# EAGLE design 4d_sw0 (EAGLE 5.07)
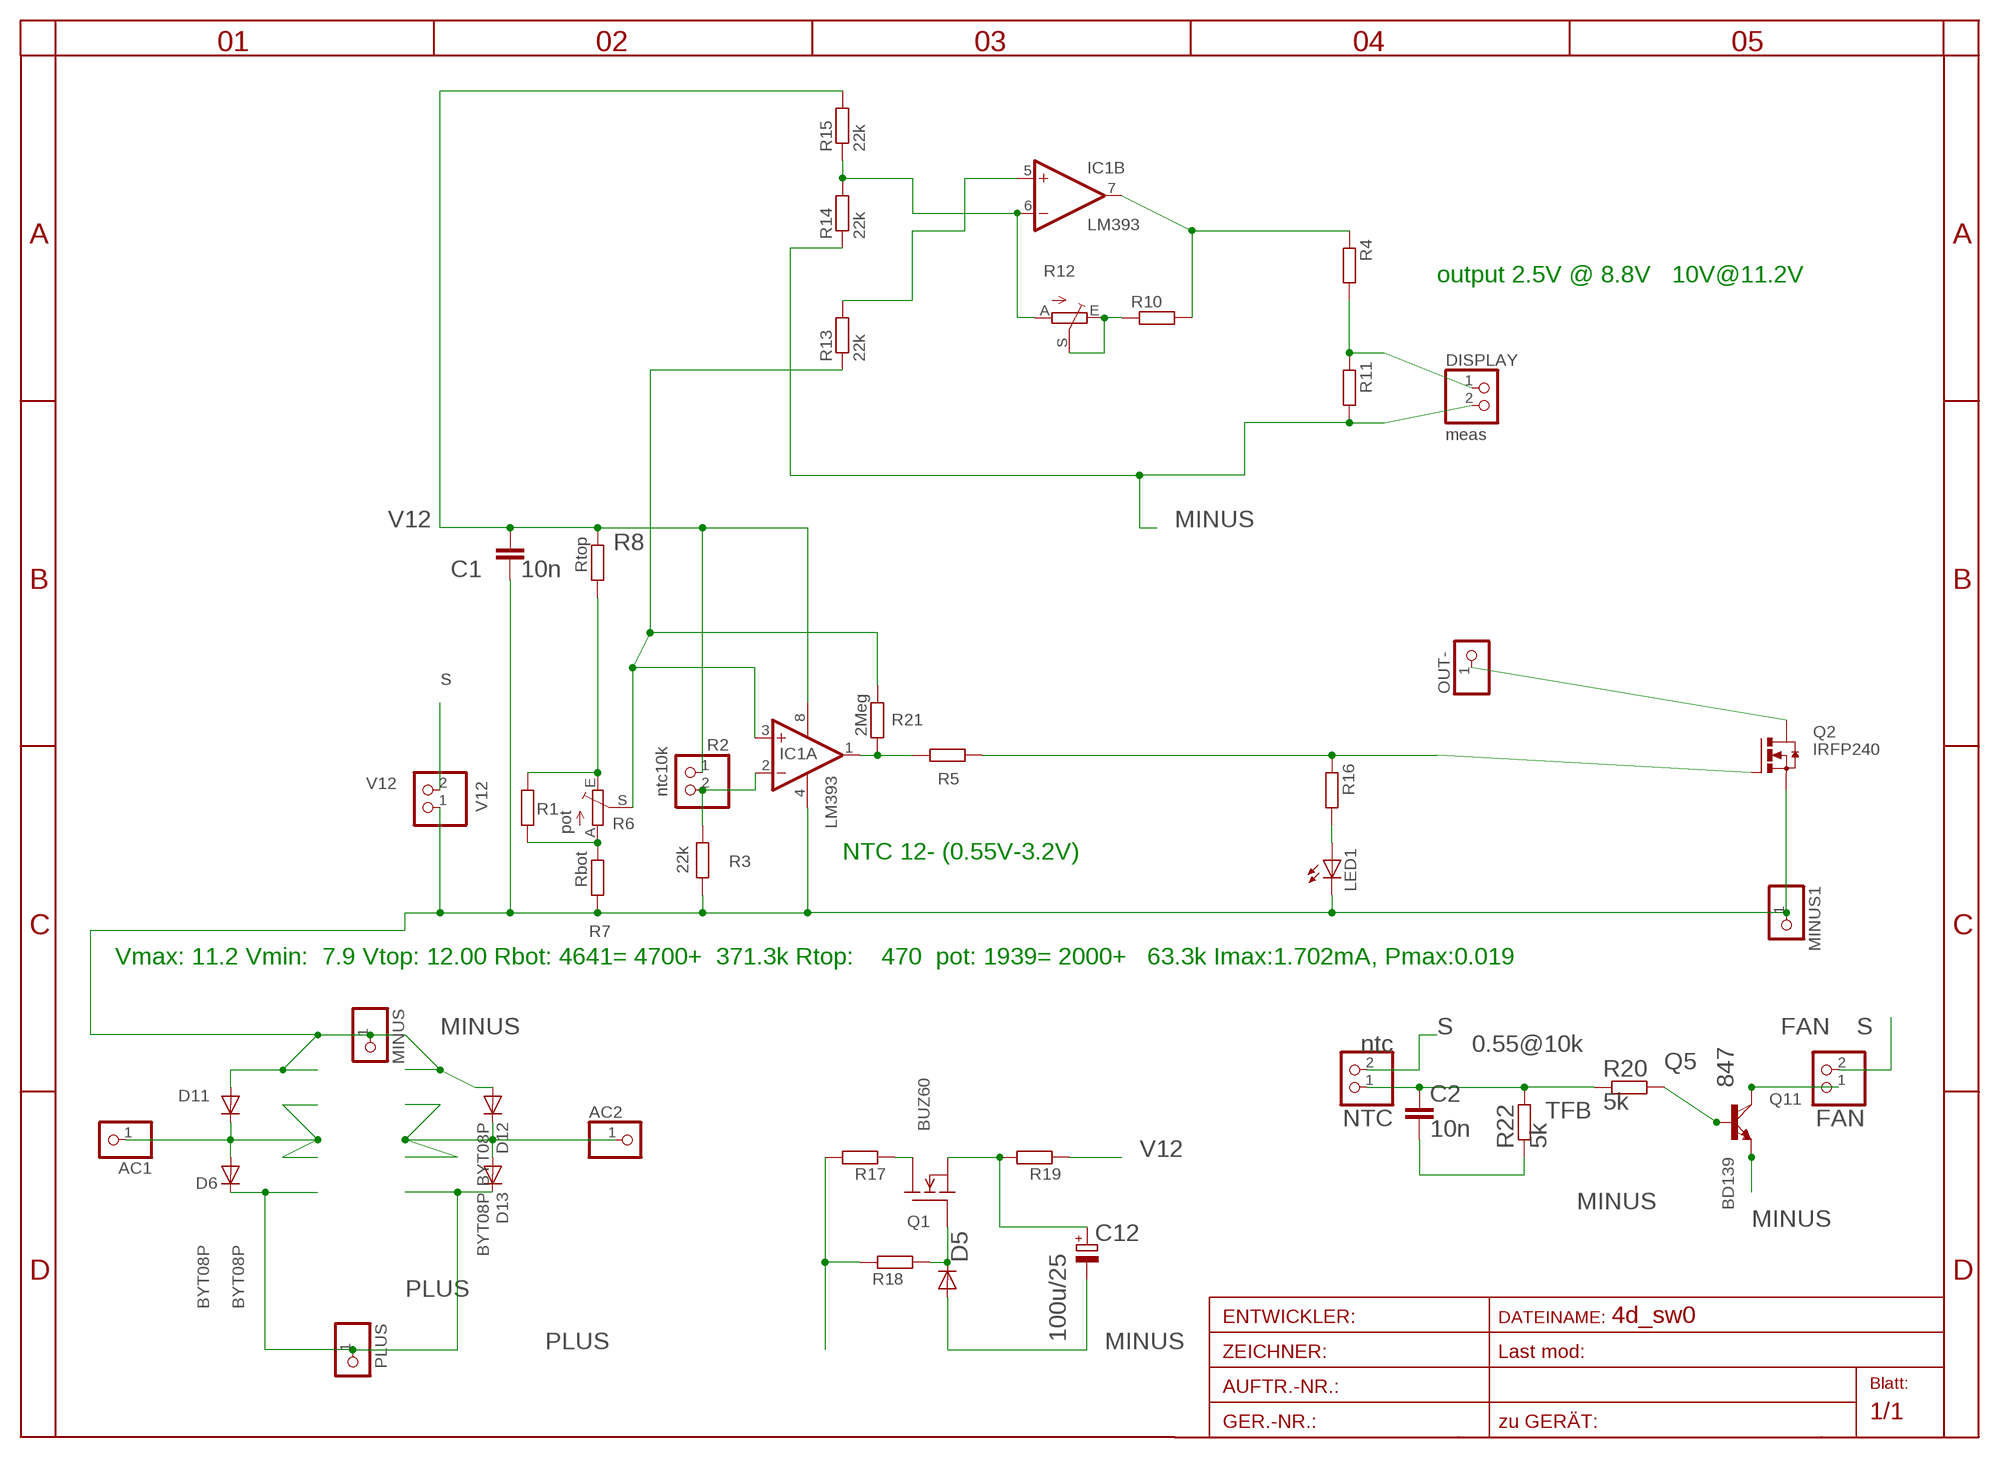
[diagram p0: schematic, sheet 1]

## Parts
AC1  PINHD-1X12MM2  [1X2MM2]
AC2  PINHD-1X12MM2  [1X2MM2]
C1  10n  C-EUC0805  [C0805]
C2  10n  C-EUC0805  [C0805]
C12  100u/25  CPOL-EUD  [PANASONIC_D]
D5  DIODE-MINIMELF  [MINIMELF]
D6  BYT08P  [TO220ACS]
D11  BYT08P  [TO220ACS]
D12  BYT08P  [TO220ACS]
D13  BYT08P  [TO220ACS]
DISPLAY  meas  PINHD-1X2STR  [1X02]
FAN  FAN  PINHD-1X2STR  [1X02]
IC1  LM393  LM358D  [SO08]
LED1  LEDSMT1206  [1206]
MINUS  PINHD-1X12MM2  [1X2MM2]
MINUS1  PINHD-1X12MM2  [1X2MM2]
NTC  ntc  PINHD-1X2STR  [1X02]
OUT-  PINHD-1X12MM2  [1X2MM2]
PLUS  PINHD-1X12MM2  [1X2MM2]
Q1  BUZ60  [TO220]
Q2  IRFP240  [TO247BV]
Q5  847  BC847SMD  [SOT23]
Q11  BD139  [TO126AV]
R1  R-EU_R1206  [R1206]
R2  ntc10k  PINHD-1X2STR  [1X02]
R3  22k  R-EU_R1206  [R1206]
R4  R-EU_R0805  [R0805]
R5  R-EU_0207-17  [0207/17]
R6  pot  TRIM_EU-RAND160  [RANDL]
R7  Rbot  R-EU_R1206  [R1206]
R8  Rtop  R-EU_R1206  [R1206]
R10  R-EU_R0805  [R0805]
R11  R-EU_R0805  [R0805]
R12  TRIM_EU-CA6V  [CA6V]
R13  22k  R-EU_R0805  [R0805]
R14  22k  R-EU_R0805  [R0805]
R15  22k  R-EU_R1206  [R1206]
R16  R-EU_R1206  [R1206]
R17  R-EU_0207/10  [0207/10]
R18  R-EU_0207/12  [0207/12]
R19  R-EU_0204/7  [0204/7]
R20  5k  R-EU_R0805  [R0805]
R21  2Meg  R-EU_R1206  [R1206]
R22  5k  R-EU_R0805  [R0805]
V12  V12  PINHD-1X2STR  [1X02]

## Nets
A: R1.2 R6.A R7.1
AC1: AC1.1 D6.A D11.C
AC2: AC2.1 D12.C D13.A
E: R1.1 R6.E R8.2
KKK: IC1.6(B:-IN) R12.A R14.2 R15.1
MINUS: C1.2 C2.2 C12.- D5.A D11.A D12.A DISPLAY.2 IC1.4(P:V-) LED1.C MINUS1.1 MINUS.1 Q2.S Q5.2(E) Q11.E R3.2 R7.2 R11.2 R14.1 R22.1 V12.1
N$1: DISPLAY.1 R4.2 R11.1
N$3: IC1.1(A:OUT) R5.2 R21.2
N$4: R10.1 R12.E R12.S
N$5: IC1.2(A:-IN) R2.2 R3.1
N$6: Q2.G R5.1 R16.1
N$7: FAN.1 Q5.3(C) Q11.C
N$8: OUT-.1 Q2.D
N$9: IC1.3(A:+IN) R6.S R13.1 R21.1
N$10: Q1.2(D) R17.1
N$11: IC1.7(B:OUT) R4.1 R10.2
N$12: D5.C Q1.1(G) R18.1
N$13: Q5.1(B) Q11.B R20.2
N$14: LED1.A R16.2
N$16: IC1.5(B:+IN) R13.2
PLUS: D6.C D13.C PLUS.1 R17.2 R18.2
S: C12.+ FAN.2 NTC.2 Q1.3(S) R19.2 V12.2
TFB: C2.1 NTC.1 R20.1 R22.2
V12: C1.1 IC1.8(P:V+) R2.1 R8.1 R15.2 R19.1

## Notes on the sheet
- output 2.5V @ 8.8V   10V@11.2V
- NTC 12- (0.55V-3.2V)
- Vmax: 11.2 Vmin:  7.9 Vtop: 12.00 Rbot: 4641= 4700+  371.3k Rtop:    470  pot: 1939= 2000+   63.3k Imax:1.702mA, Pmax:0.019
- 0.55@10k

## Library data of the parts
AC1 AC2 MINUS MINUS1 OUT- PLUS = pinhead:PINHD-1X1: PIN HEADER
C1 C2 = rcl:C-EU: CAPACITOR, European symbol
C12 = rcl:CPOL-EU: POLARIZED CAPACITOR, European symbol
D5 = diode:DIODE-: DIODE
D6 D11-D13 = diode:BYT08P: DIODE
DISPLAY FAN NTC R2 V12 = pinhead:PINHD-1X2: PIN HEADER
IC1 = linear:LM358: OP AMP also LM158; LM258; LM2904 Source: http://cache.national.com/ds/LM/LM158.pdf
LED1 = led:LED: LED
Q1 = transistor-fet(2):BUZ60: N-Channel Enhancement MOSFET 400V; 5,5A; 1,0Ohm
Q2 = transistor-power:IRFP240: HEXFET Power MosFet Source: http://www.irf.com/
Q5 = transistor-npn:BC847*: NPN Transistor
Q11 = transistor-power:BD139: NPN TRANSISTOR
R1 R3-R5 R7 R8 R10 R11 R13-R22 = rcl:R-EU_: RESISTOR, European symbol
R6 R12 = pot:TRIM_EU-: POTENTIOMETER

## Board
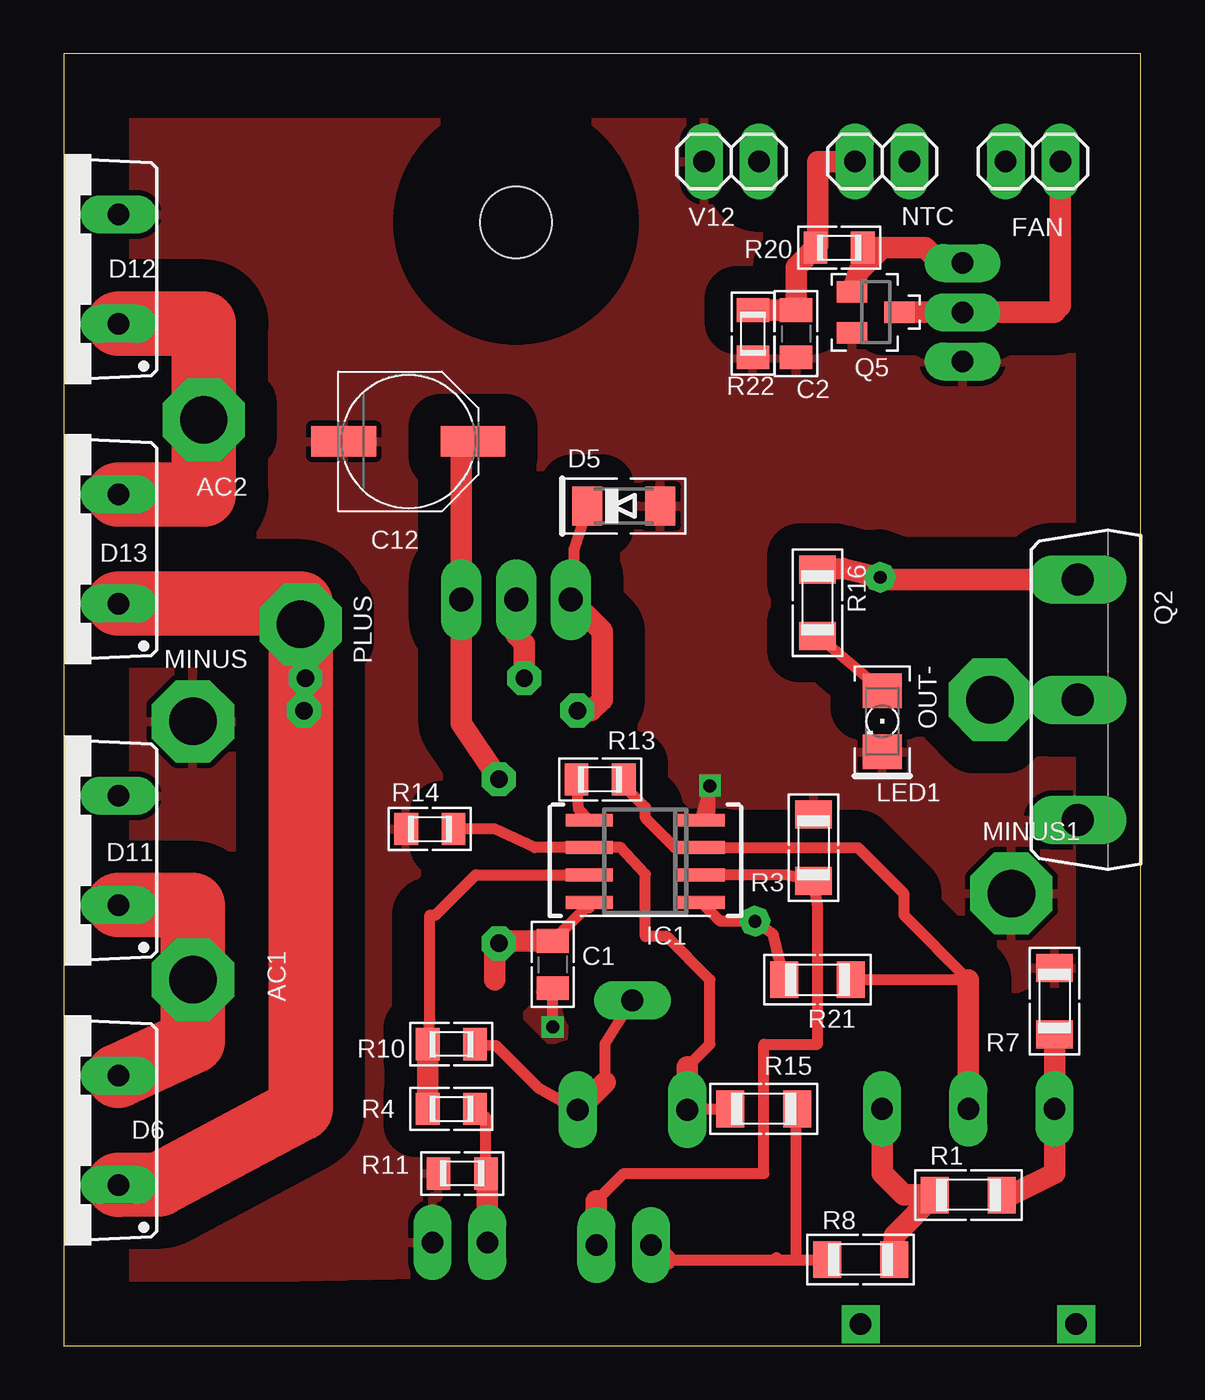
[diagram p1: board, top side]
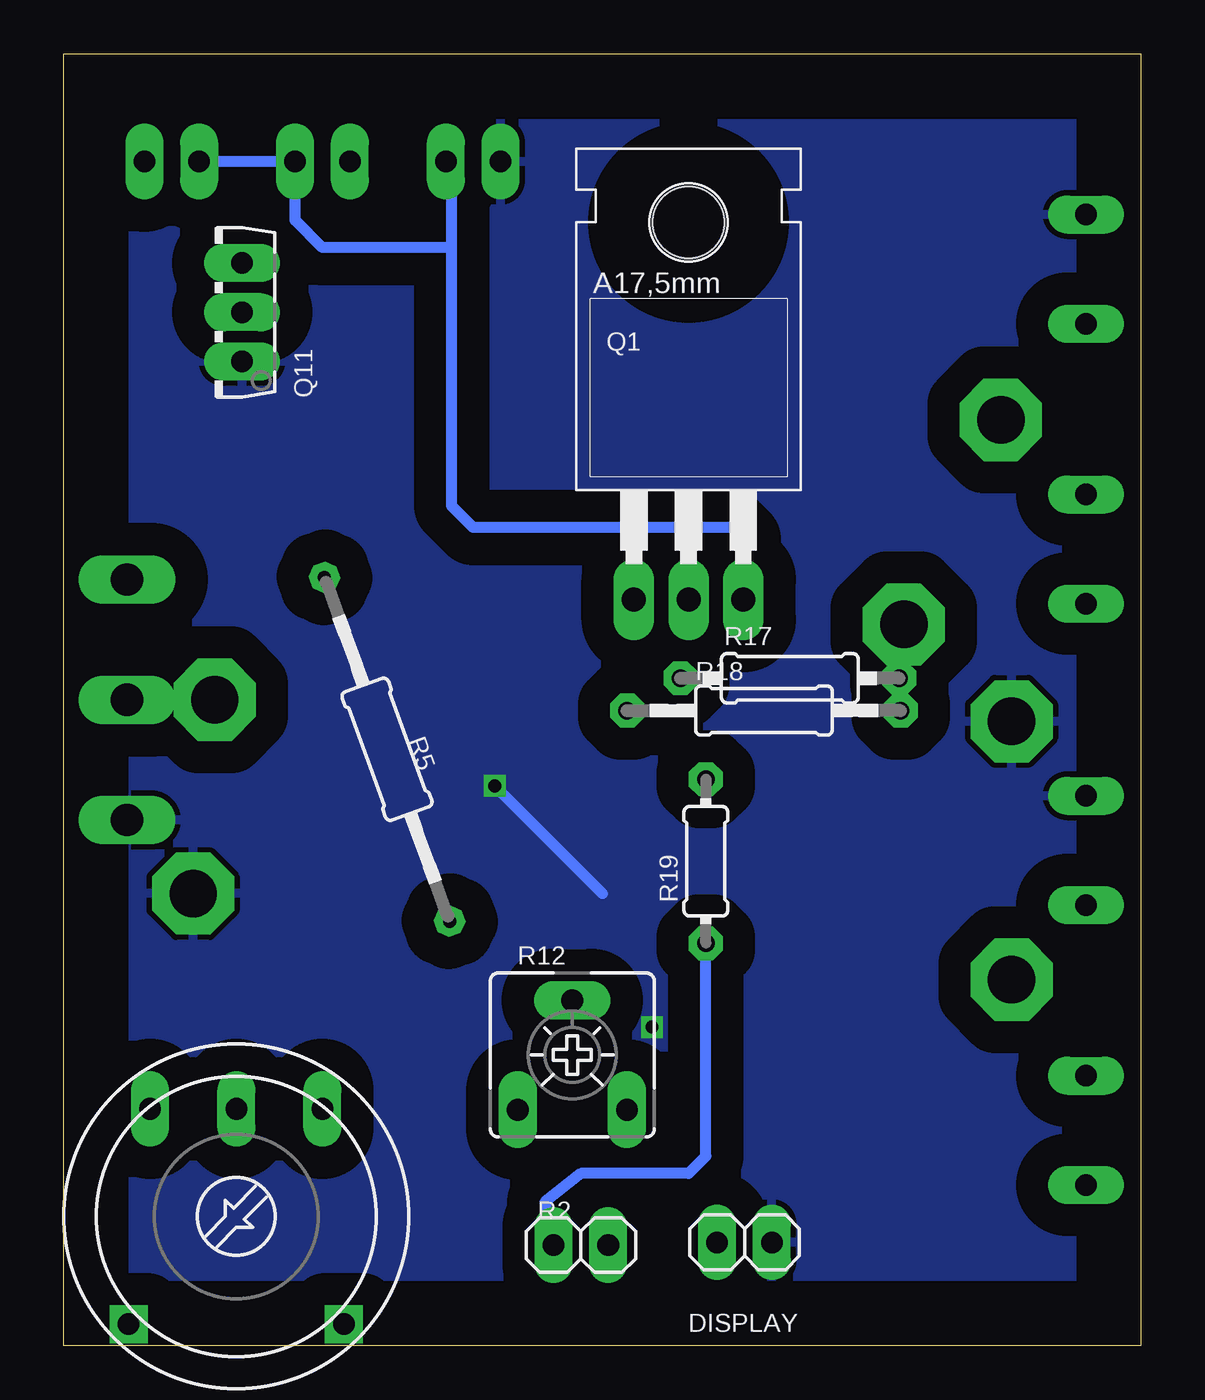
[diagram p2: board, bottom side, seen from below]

Size 50 x 60 mm. Coordinates in mm from the lower left corner, seen from the top.
Outline: 0,0 50,0 50,60 0,60 0,0
Copper layers (1*16): Top 0.035mm / dielectric 1.5mm / Bottom 0.035mm
Design rules "default *": minimum track width 10mil, minimum drill 20mil, track to track 8mil, track to pad 8mil, pad to pad 8mil, via to via 8mil, smd to smd 8mil, copper to edge 3mm, drill to drill 8mil, minimum pad ring 15mil, minimum via ring 8mil, stop-mask expansion 4mil, vias tented up to drill 0mil, thermal gap 10mil

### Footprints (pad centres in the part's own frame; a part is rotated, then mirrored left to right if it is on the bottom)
1X2MM2 = drill 2.2 pad 3.81 octagon: 1 0,0
C0805 = smd 1.1 x 1.5: 1 -1.1,0; 2 1.1,0
PANASONIC_D = smd 3 x 1.4: + 3,0; - -3,0
MINIMELF = smd 1.4 x 1.8: A 1.7,0; C -1.7,0
TO220ACS = drill 1 pad 1.676 long: A 2.54,-2.54; C -2.54,-2.54
1X02 = drill 1 pad 1.676 long: 1 -1.27,0; 2 1.27,0
SO08 = smd 0.6 x 2.2: 1 -1.905,-2.6; 2 -0.635,-2.6; 3 0.635,-2.6; 4 1.905,-2.6; 5 1.905,2.6; 6 0.635,2.6; 7 -0.635,2.6; 8 -1.905,2.6
1206 = smd 1.6 x 1.803: A -1.422,0; C 1.422,0
TO220 = drill 1.118 long: 1 -2.54,-6.35; 2 0,-6.35; 3 2.54,-6.35 | hole 3.302: 0,11.176
TO247BV = drill 1.499 long: D 0,-2.921; G -5.588,-2.921; S 5.588,-2.921
SOT23 = smd 1 x 1.4: 1 -0.95,-1.1; 2 0.95,-1.1; 3 0,1.1
TO126AV = drill 1 pad 1.27 long: B 2.286,-1.27; C 0,-1.27; E -2.286,-1.27
R1206 = smd 1.3 x 1.7: 1 -1.55,0; 2 1.55,0
R0805 = smd 1.1 x 1.5: 1 -1.1,0; 2 1.1,0
0207/17 = drill 0.6 octagon: 1 -8.5,0; 2 8.5,0
RANDL = drill 1 long: A -4,5; E 4,5; S 0,5 | drill 1 square: P$1 -5,-5; P$2 5,-5
CA6V = drill 1.016 long: A -2.54,-2.54; E 2.54,-2.54; S 0,2.54
0207/10 = drill 0.8 octagon: 1 -5.08,0; 2 5.08,0
0207/12 = drill 0.813 octagon: 1 -6.35,0; 2 6.35,0
0204/7 = drill 0.813 octagon: 1 -3.81,0; 2 3.81,0

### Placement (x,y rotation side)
AC1  6,17 270 top
AC2  6.5,43 0 top
C1  22.7,17.7 270 top
C2  34,47 270 top
C12  16,42 0 top
D5  26,39 0 top
D6  0,10 90 top
D11  0,23 90 top
D12  0,50 90 top
D13  0,37 90 top
DISPLAY  18.4,4.8 0 bottom
FAN  45,55 180 top
IC1  27,22.5 90 top
LED1  38,29 270 top
MINUS  6,29 0 top
MINUS1  44,21 0 top
NTC  38,55 0 top
OUT-  43,30 90 top
PLUS  11,33.5 270 top
Q1  21,41 0 bottom
Q2  50,30 270 top
Q5  37.7,48 270 top
Q11  43,48 90 bottom
R1  42,7 0 top
R2  26,4.67 0 bottom
R3  34.81,23.13 90 top
R4  18,11 0 top
R5  35,27.7 290 bottom
R6  42,6 0 bottom
R7  46,16 90 top
R8  37,4 0 top
R10  18,14 180 top
R11  18.5,8 180 top
R12  26.4,13.5 0 bottom
R13  24.9,26.3 180 top
R14  17,24 0 top
R15  32.5,11 0 top
R16  35,34.5 270 top
R17  16.3,31 0 bottom
R18  17.5,29.5 0 bottom
R19  20.2,22.5 90 bottom
R20  36,51 0 top
R21  35,17 180 top
R22  32,47 90 top
V12  31,55 0 top

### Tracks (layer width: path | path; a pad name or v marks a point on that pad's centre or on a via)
A
  Top 1: R1.2 44,7 46,8 R6.A R7.1
AC1
  Top 3: D6.A 6,14.14 AC1.1 6,20.46 D11.C
AC2
  Top 3: D12.C 6.5,47.46 AC2.1 6.5,39.54 D13.A
E
  Top 1: R8.2 38.55,5.1 R1.1 39,7 38,8 R6.E
KKK
  Top 0.5: 28.94,12.94 30,14 30,17 28,19 27,19 27,21.9 25.86,23.14 IC1.6 21.86,23.14 20,24 R14.2 | R15.1 28.98,11 R12.A
  Top 1: R12.A 28.94,12.94
MINUS  (via drill 0.6)
  Top 0.5: v22.7,14.8 C1.2 | 29.6,24.6 IC1.4 30,24.8 v30,26 29.6,24.6
  Bottom 0.5: 25,21 v30,26
  pour Bottom (isolate 1.5): 15,59 48,59 48,3 0,2 -1,57
  pour Top (isolate 1.5): 17,60 50,60 50,4 2,3 1,58
N$1
  Top 0.5: R11.1 19.6,10.6 R4.2
  Top 1: DISPLAY.1 19.67,8.17 R11.1
N$3
  Top 0.5: R21.2 32.95,19.1 R5.2 30.48,19.71 IC1.1
N$4
  Top 0.5: R12.S 25.14,14.04 25.14,12.24 | R12.E 22,12 20.06,13.94 19.96,13.94 R10.1
  Top 1: R12.E 25.14,12.24
N$5
  Top 0.5: 24.73,6.73 26,8 32.5,8 32.5,14 35,14 35,20.39 R3.1 33.52,21.86 IC1.2
  Top 1: R2.2 24.73,6.73
N$6
  Top 1: Q2.G 37.71,35.59 R5.1 36.2,36.09 R16.1
N$7
  Top 1: Q5.3 Q11.C 46,48 46.27,48.27 FAN.1
N$8
  Top 0.5: OUT-.1 Q2.D
N$9
  Top 0.5: R13.1 26.1,25.9 27,25 27,24.5 28.36,23.14 IC1.3 36.87,23.14 39,21 39,20 42,17 R21.1
  Top 1: 42,17 R6.S
N$10
  Top 1: R17.1 21.38,32.62 21,33 Q1.2
N$11
  Top 0.5: R10.2 17,15.1 17,20 17.27,20 19.14,21.86 IC1.7
  Top 1: R4.1 R10.2
N$12
  Top 0.5: Q1.1 23.65,34.65 23.7,37 24.2,38.5 D5.C
  Top 1: R18.1 24.5,29.5 25,30 25,33.19 Q1.1
N$13
  Top 1: Q11.B 40.71,50.29 40,51 38,51 | 38,51 R20.2 | Q5.1 36.9,49.9 38,51
N$14
  Top 0.5: R16.2 LED1.A
N$16
  Top 0.5: R13.2 23.9,24.91 IC1.5
PLUS
  Top 0.5: R18.2 11.15,30.93 R17.2 11.22,32.78 11,33
  Top 3: D6.C 4.44,7.5 11,11 11,33 PLUS.1 11,34.46 D13.C
S
  Top 1: R19.2 18.46,28.9 Q1.3 18.46,41.46 C12.+
  Bottom 0.5: Q1.3 18.46,37.46 19,38 31,38 32,39 32,51 | 32,51 32,54.73 V12.2 | 32,51 38,51 39.27,52.27 NTC.2 FAN.2
TFB
  Top 1: NTC.1 35,55 35,51.1 R20.1 34,50.1 C2.1 R22.2
V12
  Top 0.5: 27.94,4 33,4 | 33,4 34,4 | 34,4 R8.1 | 33,4 33.1,4.1 | IC1.8 24.4,20.35 24.25,20.35 C1.1 | R15.2 34.05,10.65 34,10 34,4
  Top 1: R2.1 27.94,4 | 20,17 20,18.69 R19.1 20.2,18.8 C1.1
  Bottom 0.5: R2.1 27.67,6.67 26,8 21,8 20.2,8.8 R19.1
